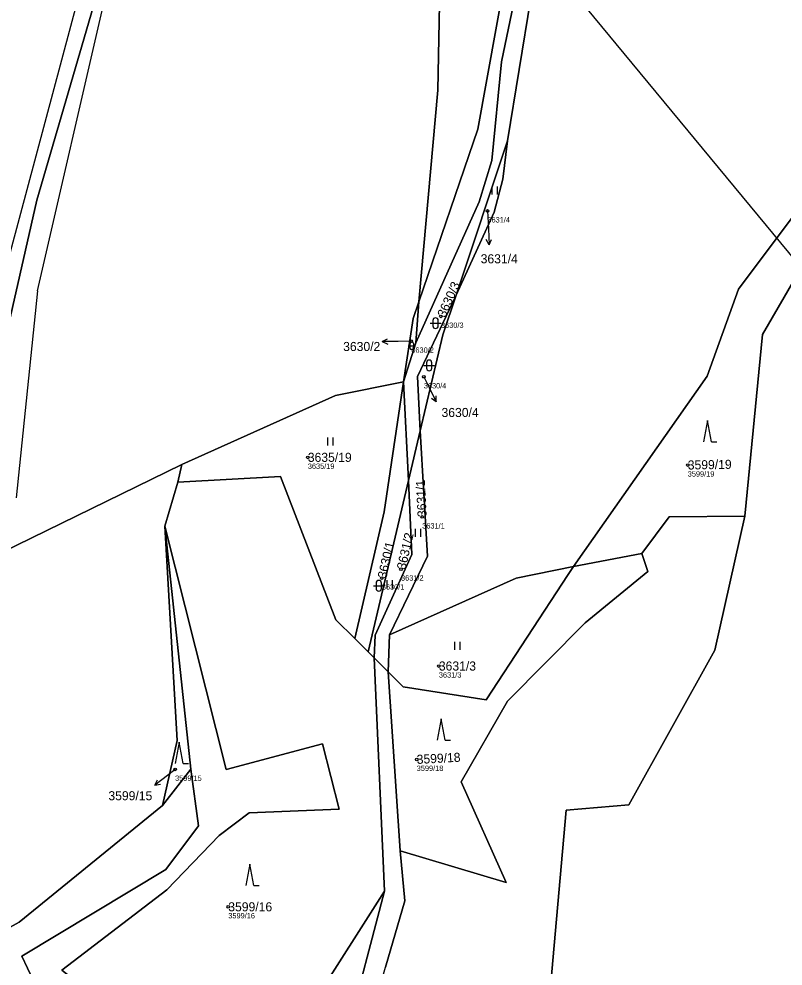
# Model space of a CAD drawing. Extents: x -761174 to -757114, y -1063806 to -1059397.
# Drawn here: x -759812.1 to -759669, y -1062320.9 to -1062143.6 of the extents above; entities that cross this region are included whole.
import ezdxf

# ---------------------------------------------------------------- set-up
doc = ezdxf.new("R2010")
doc.units = 0
for name, color, linetype in [('Definiční body', 7, 'Continuous'), ('Hranice parcel', 7, 'Continuous'), ('Parcelní čísla', 7, 'Continuous'), ('Polygon parcely', 7, 'Continuous'), ('Pop  PČ popisy', 7, 'Continuous'), ('Poz předměty', 7, 'Continuous'), ('Vnitřní kresba', 7, 'Continuous'), ('Značky kultur', 7, 'Continuous')]:
    doc.layers.add(name, color=color, linetype=linetype)

msp = doc.modelspace()

# ---------------------------------------------------------------- linework, layer by layer
at = {"layer": 'Definiční body'}
for centre in [(-759724.36, -1062179.54), (-759733.05, -1062199.28), (-759738.61, -1062203.93), (-759736.27, -1062210.61), (-759757.99, -1062225.68), (-759686.85, -1062227.12), (-759736.57, -1062236.85), (-759740.54, -1062246.61), (-759744.13, -1062248.28), (-759733.45, -1062264.76), (-759737.6, -1062282.25), (-759782.84, -1062284.11), (-759772.88, -1062309.85)]:
    msp.add_circle(centre, 0.25, dxfattribs=at)
at = {"layer": 'Hranice parcel'}
for p, q in [((-759720.61, -1062166.43), (-759716.25, -1062139.61)), ((-759730.24, -1062195.31), (-759720.61, -1062166.43)), ((-759737.74, -1062204.26), (-759737.22, -1062196.58)), ((-759740.05, -1062211.53), (-759737.74, -1062204.26)), ((-759739.14, -1062230.01), (-759740.05, -1062211.53)), ((-759739.14, -1062230.01), (-759736.96, -1062220.72)), ((-759781.6, -1062227.04), (-759815.38, -1062243.59)), ((-759782.35, -1062230.32), (-759781.6, -1062227.04)), ((-759782.35, -1062230.32), (-759784.74, -1062238.57)), ((-759746.7, -1062262.09), (-759739.14, -1062230.01)), ((-759784.74, -1062238.57), (-759779.89, -1062284.06)), ((-759695.44, -1062243.68), (-759708.22, -1062246.11)), ((-759746.7, -1062262.09), (-759749.18, -1062259.62)), ((-759742.96, -1062265.82), (-759742.68, -1062258.9)), ((-759745.54, -1062263.25), (-759746.7, -1062262.09)), ((-759742.96, -1062265.82), (-759745.54, -1062263.25)), ((-759745.54, -1062263.25), (-759743.66, -1062306.91)), ((-759740.67, -1062299.37), (-759742.96, -1062265.82)), ((-759779.89, -1062284.06), (-759785.19, -1062290.87))]:
    msp.add_line(p, q, dxfattribs=at)
for points in [[(-759545.3, -1061775.92), (-759556.69, -1061808.62), (-759569.81, -1061839.63), (-759636.3, -1061992.96), (-759657.95, -1062035.02), (-759667.29, -1062048.77), (-759718.51, -1062136.23), (-759721.74, -1062151.6), (-759723.54, -1062170.11), (-759725.88, -1062177.84), (-759737.74, -1062204.26)], [(-759558.92, -1061800.74), (-759575.13, -1061841.03), (-759591.11, -1061875.72), (-759612.9, -1061925.74), (-759639.46, -1061986.58), (-759648.39, -1062006.27), (-759683.61, -1062069.8), (-759720.86, -1062134.89), (-759726.17, -1062164.23), (-759737.22, -1062196.58)], [(-759815.38, -1062243.59), (-759815.76, -1062232.79), (-759816.51, -1062211.67), (-759808.74, -1062177.53), (-759796.88, -1062136.8), (-759772.79, -1062042.32), (-759754.06, -1061970.78)], [(-759737.22, -1062196.58), (-759733.65, -1062156.94), (-759733.29, -1062137.53), (-759733.29, -1062120.99), (-759730.77, -1062101.04), (-759728.98, -1062091.69), (-759727.54, -1062084.5), (-759716.22, -1062052.87), (-759689.95, -1061989.47)], [(-759730.24, -1062195.31), (-759723.11, -1062179.76), (-759721.45, -1062173.6), (-759720.61, -1062166.43)], [(-759656.65, -1062166.55), (-759677.32, -1062194.16), (-759683.22, -1062210.47), (-759708.22, -1062246.11)], [(-759676.15, -1062236.72), (-759672.84, -1062202.65), (-759655.22, -1062172.34), (-759631.4, -1062166.18)], [(-759736.96, -1062220.72), (-759737.42, -1062210.53), (-759730.24, -1062195.31)], [(-759736.96, -1062220.72), (-759732.72, -1062202.74), (-759730.24, -1062195.31)], [(-759737.22, -1062196.58), (-759738.27, -1062199.65), (-759740.05, -1062211.53)], [(-759781.6, -1062227.04), (-759752.83, -1062214.13), (-759740.05, -1062211.53)], [(-759740.05, -1062211.53), (-759743.7, -1062235.88), (-759749.18, -1062259.62)], [(-759742.68, -1062258.9), (-759735.59, -1062244.19), (-759736.96, -1062220.72)], [(-759749.18, -1062259.62), (-759752.72, -1062256.09), (-759763.1, -1062229.27), (-759782.35, -1062230.32)], [(-759739.14, -1062230.01), (-759738.49, -1062243.89), (-759745.4, -1062258.95), (-759745.54, -1062263.25)], [(-759661.11, -1062333.69), (-759655, -1062355.31), (-759665.48, -1062372.16), (-759707.86, -1062386.9), (-759714.53, -1062347.36), (-759709.59, -1062291.77), (-759697.9, -1062290.77), (-759681.77, -1062261.79), (-759676.15, -1062236.72)], [(-759676.15, -1062236.72), (-759690.31, -1062236.81), (-759695.44, -1062243.68)], [(-759781.89, -1062360.97), (-759792.16, -1062330.99), (-759804.08, -1062321.72), (-759784.37, -1062306.65), (-759774.58, -1062296.47), (-759768.98, -1062292.24), (-759752.09, -1062291.57), (-759755.23, -1062279.32), (-759773.28, -1062284.12), (-759784.74, -1062238.57)], [(-759784.74, -1062238.57), (-759782.46, -1062278.72), (-759785.19, -1062290.87)], [(-759695.44, -1062243.68), (-759694.32, -1062247.04), (-759706.04, -1062256.65), (-759720.57, -1062271.35), (-759729.26, -1062286.46), (-759720.82, -1062305.3), (-759740.67, -1062299.37)], [(-759708.22, -1062246.11), (-759709.26, -1062247.6), (-759724.58, -1062271.1), (-759740.12, -1062268.66), (-759742.96, -1062265.82)], [(-759708.22, -1062246.11), (-759719, -1062248.31), (-759742.68, -1062258.9)], [(-759807.29, -1062328.11), (-759811.57, -1062319.1), (-759784.56, -1062302.86), (-759778.43, -1062294.67), (-759779.89, -1062284.06)], [(-759785.19, -1062290.87), (-759812.06, -1062312.74), (-759841.45, -1062329.06), (-759887.14, -1062348.41), (-759932.19, -1062365.38), (-759967.88, -1062383.64)], [(-760020.59, -1062648.57), (-759995.77, -1062595.56), (-759991.2, -1062568.04), (-759996.63, -1062541.3), (-759992.35, -1062525.36), (-759974.46, -1062506.7), (-759909.51, -1062464.71), (-759859.16, -1062431.43), (-759834.95, -1062413.73), (-759801.17, -1062385.56), (-759794.9, -1062381.81), (-759778.11, -1062375.37), (-759761.36, -1062358.58), (-759747.99, -1062337.03), (-759743.43, -1062321.15), (-759739.84, -1062308.74), (-759740.67, -1062299.37)], [(-759743.66, -1062306.91), (-759750.82, -1062334.23), (-759753.96, -1062339.82), (-759764.09, -1062355.43), (-759780.18, -1062372.22), (-759794.64, -1062378.4)], [(-759781.89, -1062360.97), (-759776.24, -1062342.1), (-759767.38, -1062331.67), (-759756.89, -1062327.68), (-759743.66, -1062306.91)]]:
    msp.add_lwpolyline(points, dxfattribs=at)
at = {"layer": 'Polygon parcely'}
for points in [[(-759558.92, -1061800.74), (-759595.48, -1061771.75), (-759611.84, -1061811.14), (-759629.14, -1061861.06), (-759642.77, -1061894.86), (-759665.68, -1061944.54), (-759687.02, -1061992.16), (-759689.95, -1061989.47), (-759716.22, -1062052.87), (-759727.54, -1062084.5), (-759728.98, -1062091.69), (-759730.77, -1062101.04), (-759733.29, -1062120.99), (-759733.29, -1062137.53), (-759733.65, -1062156.94), (-759737.22, -1062196.58), (-759726.17, -1062164.23), (-759720.86, -1062134.89), (-759683.61, -1062069.8), (-759648.39, -1062006.27), (-759639.46, -1061986.58), (-759612.9, -1061925.74), (-759591.11, -1061875.72), (-759575.13, -1061841.03)], [(-759648.39, -1062006.27), (-759683.61, -1062069.8), (-759720.86, -1062134.89), (-759726.17, -1062164.23), (-759737.22, -1062196.58), (-759737.74, -1062204.26), (-759725.88, -1062177.84), (-759723.54, -1062170.11), (-759721.74, -1062151.6), (-759718.51, -1062136.23), (-759667.29, -1062048.77), (-759657.95, -1062035.02), (-759636.3, -1061992.96), (-759569.81, -1061839.63), (-759556.69, -1061808.62), (-759545.3, -1061775.92), (-759550.13, -1061774.5), (-759553.55, -1061786.76), (-759558.92, -1061800.74), (-759575.13, -1061841.03), (-759591.11, -1061875.72), (-759612.9, -1061925.74), (-759639.46, -1061986.58)], [(-759730.77, -1062101.04), (-759728.98, -1062091.69), (-759727.54, -1062084.5), (-759716.22, -1062052.87), (-759689.95, -1061989.47), (-759687.6, -1061983.6), (-759718.19, -1061977.43), (-759750.64, -1061971.41), (-759754.06, -1061970.78), (-759772.79, -1062042.32), (-759796.88, -1062136.8), (-759808.74, -1062177.53), (-759816.51, -1062211.67), (-759815.76, -1062232.79), (-759815.38, -1062243.59), (-759781.6, -1062227.04), (-759752.83, -1062214.13), (-759740.05, -1062211.53), (-759738.27, -1062199.65), (-759737.22, -1062196.58), (-759733.65, -1062156.94), (-759733.29, -1062137.53), (-759733.29, -1062120.99)], [(-759588.26, -1062010.59), (-759631.6, -1061990.87), (-759640.77, -1062012.48), (-759677.67, -1062073.75), (-759716.25, -1062139.61), (-759720.61, -1062166.43), (-759721.45, -1062173.6), (-759723.11, -1062179.76), (-759730.24, -1062195.31), (-759732.72, -1062202.74), (-759736.96, -1062220.72), (-759735.59, -1062244.19), (-759742.68, -1062258.9), (-759719, -1062248.31), (-759708.22, -1062246.11), (-759683.22, -1062210.47), (-759677.32, -1062194.16), (-759656.65, -1062166.55), (-759629.93, -1062140.56), (-759592.55, -1062105.98), (-759580.43, -1062086.92), (-759557.69, -1062026.84)], [(-759721.45, -1062173.6), (-759720.61, -1062166.43), (-759730.24, -1062195.31), (-759723.11, -1062179.76)], [(-759655.22, -1062172.34), (-759631.4, -1062166.18), (-759656.65, -1062166.55), (-759677.32, -1062194.16), (-759683.22, -1062210.47), (-759708.22, -1062246.11), (-759695.44, -1062243.68), (-759690.31, -1062236.81), (-759676.15, -1062236.72), (-759672.84, -1062202.65)], [(-759736.96, -1062220.72), (-759732.72, -1062202.74), (-759730.24, -1062195.31), (-759737.42, -1062210.53)], [(-759737.74, -1062204.26), (-759737.22, -1062196.58), (-759738.27, -1062199.65), (-759740.05, -1062211.53)], [(-759782.35, -1062230.32), (-759763.1, -1062229.27), (-759752.72, -1062256.09), (-759749.18, -1062259.62), (-759743.7, -1062235.88), (-759740.05, -1062211.53), (-759752.83, -1062214.13), (-759781.6, -1062227.04)], [(-759743.7, -1062235.88), (-759749.18, -1062259.62), (-759746.7, -1062262.09), (-759739.14, -1062230.01), (-759740.05, -1062211.53)], [(-759745.4, -1062258.95), (-759745.54, -1062263.25), (-759742.96, -1062265.82), (-759742.68, -1062258.9), (-759735.59, -1062244.19), (-759736.96, -1062220.72), (-759739.14, -1062230.01), (-759738.49, -1062243.89)], [(-759756.89, -1062327.68), (-759743.66, -1062306.91), (-759745.54, -1062263.25), (-759746.7, -1062262.09), (-759749.18, -1062259.62), (-759752.72, -1062256.09), (-759763.1, -1062229.27), (-759782.35, -1062230.32), (-759784.74, -1062238.57), (-759773.28, -1062284.12), (-759755.23, -1062279.32), (-759752.09, -1062291.57), (-759768.98, -1062292.24), (-759774.58, -1062296.47), (-759784.37, -1062306.65), (-759804.08, -1062321.72), (-759792.16, -1062330.99), (-759781.89, -1062360.97), (-759776.24, -1062342.1), (-759767.38, -1062331.67)], [(-759746.7, -1062262.09), (-759745.54, -1062263.25), (-759745.4, -1062258.95), (-759738.49, -1062243.89), (-759739.14, -1062230.01)], [(-759784.74, -1062238.57), (-759782.46, -1062278.72), (-759785.19, -1062290.87), (-759779.89, -1062284.06)], [(-759740.12, -1062268.66), (-759742.96, -1062265.82), (-759740.67, -1062299.37), (-759720.82, -1062305.3), (-759729.26, -1062286.46), (-759720.57, -1062271.35), (-759706.04, -1062256.65), (-759694.32, -1062247.04), (-759695.44, -1062243.68), (-759708.22, -1062246.11), (-759709.26, -1062247.6), (-759724.58, -1062271.1)], [(-759708.22, -1062246.11), (-759719, -1062248.31), (-759742.68, -1062258.9), (-759742.96, -1062265.82), (-759740.12, -1062268.66), (-759724.58, -1062271.1), (-759709.26, -1062247.6)], [(-759932.19, -1062365.38), (-759967.88, -1062383.64), (-759942.48, -1062419.16), (-760023, -1062468.21), (-760010.32, -1062480.46), (-760000.07, -1062471.78), (-759958.26, -1062448.21), (-759890.08, -1062409.72), (-759837.94, -1062374.87), (-759850.99, -1062357.55), (-759807.29, -1062328.11), (-759811.57, -1062319.1), (-759784.56, -1062302.86), (-759778.43, -1062294.67), (-759779.89, -1062284.06), (-759785.19, -1062290.87), (-759812.06, -1062312.74), (-759841.45, -1062329.06), (-759887.14, -1062348.41)], [(-759794.64, -1062378.4), (-759780.18, -1062372.22), (-759764.09, -1062355.43), (-759753.96, -1062339.82), (-759750.82, -1062334.23), (-759743.66, -1062306.91), (-759756.89, -1062327.68), (-759767.38, -1062331.67), (-759776.24, -1062342.1), (-759781.89, -1062360.97)]]:
    msp.add_lwpolyline(points, close=True, dxfattribs=at)
for points in [[(-759569.81, -1061839.63), (-759636.3, -1061992.96), (-759657.95, -1062035.02), (-759667.29, -1062048.77), (-759718.51, -1062136.23), (-759721.74, -1062151.6), (-759723.54, -1062170.11), (-759725.88, -1062177.84), (-759737.74, -1062204.26), (-759740.05, -1062211.53), (-759739.14, -1062230.01), (-759736.96, -1062220.72), (-759737.42, -1062210.53), (-759730.24, -1062195.31), (-759720.61, -1062166.43), (-759716.25, -1062139.61), (-759666.36, -1062051.73), (-759656.73, -1062037.91), (-759631.6, -1061990.87), (-759555.83, -1061812.6)], [(-759816.51, -1062211.67), (-759808.74, -1062177.53), (-759796.88, -1062136.8), (-759772.79, -1062042.32), (-759754.06, -1061970.78), (-759732.68, -1061896.84)], [(-759662.21, -1062329.2), (-759648.9, -1062270.26), (-759631.44, -1062212.08), (-759635.25, -1062195.55), (-759634.49, -1062185.46), (-759605.51, -1062154.07), (-759594.73, -1062135.75), (-759577.55, -1062116.98), (-759562.6, -1062106.42), (-759557.22, -1062097.26), (-759568.77, -1062107.25), (-759586.12, -1062114.51), (-759603.7, -1062133.56), (-759610.81, -1062145.76), (-759629.98, -1062149.51), (-759631.72, -1062157.82), (-759631.4, -1062166.18), (-759655.22, -1062172.34), (-759672.84, -1062202.65), (-759676.15, -1062236.72), (-759681.77, -1062261.79), (-759697.9, -1062290.77), (-759709.59, -1062291.77), (-759714.53, -1062347.36)], [(-759841.45, -1062329.06), (-759812.06, -1062312.74), (-759785.19, -1062290.87), (-759782.46, -1062278.72), (-759784.74, -1062238.57), (-759782.35, -1062230.32), (-759781.6, -1062227.04), (-759815.38, -1062243.59), (-759827.1, -1062249.52), (-759856.29, -1062267.96), (-759874.47, -1062278.25), (-759899.94, -1062290.42), (-759909.41, -1062270.89), (-759941.52, -1062288.27), (-759942.75, -1062286.38), (-759968.14, -1062295.03), (-760027.57, -1062313.78), (-760098.41, -1062337.59)], [(-759714.53, -1062347.36), (-759709.59, -1062291.77), (-759697.9, -1062290.77), (-759681.77, -1062261.79), (-759676.15, -1062236.72), (-759690.31, -1062236.81), (-759695.44, -1062243.68), (-759694.32, -1062247.04), (-759706.04, -1062256.65), (-759720.57, -1062271.35), (-759729.26, -1062286.46), (-759720.82, -1062305.3), (-759740.67, -1062299.37), (-759739.84, -1062308.74), (-759743.43, -1062321.15)], [(-759804.08, -1062321.72), (-759784.37, -1062306.65), (-759774.58, -1062296.47), (-759768.98, -1062292.24), (-759752.09, -1062291.57), (-759755.23, -1062279.32), (-759773.28, -1062284.12), (-759784.74, -1062238.57), (-759779.89, -1062284.06), (-759778.43, -1062294.67), (-759784.56, -1062302.86), (-759811.57, -1062319.1), (-759807.29, -1062328.11)], [(-759743.43, -1062321.15), (-759739.84, -1062308.74), (-759740.67, -1062299.37), (-759742.96, -1062265.82), (-759745.54, -1062263.25), (-759743.66, -1062306.91), (-759750.82, -1062334.23)]]:
    msp.add_lwpolyline(points, dxfattribs=at)
at = {"layer": 'Pop  PČ popisy'}
for p, q in [((-759724.36, -1062179.54), (-759724.18, -1062182.89)), ((-759724.18, -1062182.89), (-759724.02, -1062185.89)), ((-759724.02, -1062185.89), (-759724.58, -1062184.91)), ((-759724.02, -1062185.89), (-759723.58, -1062184.86)), ((-759744.04, -1062204.01), (-759743.05, -1062203.49)), ((-759741.04, -1062203.96), (-759744.04, -1062204.01)), ((-759744.04, -1062204.01), (-759743.03, -1062204.5)), ((-759738.61, -1062203.93), (-759741.04, -1062203.96)), ((-759736.27, -1062210.61), (-759735.28, -1062212.61)), ((-759735.28, -1062212.61), (-759733.96, -1062215.31)), ((-759733.96, -1062215.31), (-759734.85, -1062214.63)), ((-759733.96, -1062215.31), (-759733.95, -1062214.19)), ((-759782.84, -1062284.11), (-759784.28, -1062285.23)), ((-759784.28, -1062285.23), (-759786.65, -1062287.08)), ((-759786.65, -1062287.08), (-759786.16, -1062286.07)), ((-759786.65, -1062287.08), (-759785.55, -1062286.86))]:
    msp.add_line(p, q, dxfattribs=at)
at = {"layer": 'Poz předměty'}
msp.add_line((-759558.02, -1062320.42), (-759784.85, -1062045.77), dxfattribs=at)
at = {"layer": 'Vnitřní kresba'}
for p, q in [((-759815.09, -1062192.55), (-759798.96, -1062132.08)), ((-759808.61, -1062194.48), (-759794.27, -1062132.35)), ((-759808.61, -1062194.48), (-759812.59, -1062233.25))]:
    msp.add_line(p, q, dxfattribs=at)
at = {"layer": 'Značky kultur'}
for p, q in [((-759723.45, -1062176.48), (-759723.45, -1062174.98)), ((-759722.45, -1062176.48), (-759722.45, -1062174.98)), ((-759735.07, -1062200.56), (-759733.07, -1062200.56)), ((-759734.57, -1062200.06), (-759734.57, -1062201.06)), ((-759733.57, -1062201.06), (-759733.57, -1062200.06)), ((-759739.21, -1062204.81), (-759737.81, -1062204.81)), ((-759738.86, -1062204.46), (-759738.86, -1062205.16)), ((-759738.16, -1062205.16), (-759738.16, -1062204.46)), ((-759736.26, -1062208.47), (-759734.26, -1062208.47)), ((-759735.76, -1062207.97), (-759735.76, -1062208.97)), ((-759734.76, -1062208.97), (-759734.76, -1062207.97)), ((-759683.16, -1062218.75), (-759683.91, -1062222.75)), ((-759682.41, -1062222.75), (-759683.16, -1062218.75)), ((-759754.27, -1062223.48), (-759754.27, -1062221.98)), ((-759753.27, -1062223.48), (-759753.27, -1062221.98)), ((-759682.41, -1062222.75), (-759681.41, -1062222.75)), ((-759737.8, -1062240.57), (-759737.8, -1062239.07)), ((-759736.8, -1062240.57), (-759736.8, -1062239.07)), ((-759745.2, -1062249.22), (-759745.2, -1062250.22)), ((-759744.2, -1062250.22), (-759744.2, -1062249.22)), ((-759743.14, -1062250.21), (-759743.14, -1062248.71)), ((-759742.14, -1062250.21), (-759742.14, -1062248.71)), ((-759745.7, -1062249.72), (-759743.7, -1062249.72)), ((-759730.44, -1062261.72), (-759730.44, -1062260.22)), ((-759729.44, -1062261.72), (-759729.44, -1062260.22)), ((-759732.99, -1062274.65), (-759733.74, -1062278.65)), ((-759732.24, -1062278.65), (-759732.99, -1062274.65)), ((-759782.05, -1062279.01), (-759782.8, -1062283.01)), ((-759781.3, -1062283.01), (-759782.05, -1062279.01)), ((-759732.24, -1062278.65), (-759731.24, -1062278.65)), ((-759781.3, -1062283.01), (-759780.3, -1062283.01)), ((-759768.86, -1062301.84), (-759769.61, -1062305.84)), ((-759768.11, -1062305.84), (-759768.86, -1062301.84)), ((-759768.11, -1062305.84), (-759767.11, -1062305.84))]:
    msp.add_line(p, q, dxfattribs=at)
for centre, radius, start, end in [((-759734.07, -1062200.06), 0.5, 0, 180), ((-759734.07, -1062201.06), 0.5, 180, 359.9879), ((-759738.51, -1062204.46), 0.35, 0, 180), ((-759738.51, -1062205.16), 0.35, 180, 359.9879), ((-759735.26, -1062207.97), 0.5, 0, 180), ((-759735.26, -1062208.97), 0.5, 180, 359.9879), ((-759744.7, -1062249.22), 0.5, 0, 180), ((-759744.7, -1062250.22), 0.5, 180, 359.9879)]:
    msp.add_arc(centre, radius, start, end, dxfattribs=at)

# ---------------------------------------------------------------- texts
at = {"layer": 'Definiční body'}
for s, p in [('3631/4', (-759724.36, -1062181.7)), ('3630/3', (-759733.05, -1062201.44)), ('3630/2', (-759738.61, -1062206.09)), ('3630/4', (-759736.27, -1062212.77)), ('3635/19', (-759757.99, -1062227.84)), ('3599/19', (-759686.85, -1062229.28)), ('3631/1', (-759736.57, -1062239.01)), ('3631/2', (-759740.54, -1062248.77)), ('3630/1', (-759744.13, -1062250.44)), ('3631/3', (-759733.45, -1062266.92)), ('3599/18', (-759737.6, -1062284.41)), ('3599/15', (-759782.84, -1062286.27)), ('3599/16', (-759772.88, -1062312.01))]:
    msp.add_text(s, height=1, dxfattribs=at).set_placement(p)
at = {"layer": 'Parcelní čísla'}
for s, p in [('3631/4', (-759725.62, -1062189.35)), ('3630/2', (-759751.37, -1062205.77)), ('3630/4', (-759732.95, -1062218.13)), ('3635/19', (-759757.99, -1062226.53)), ('3631/3', (-759733.45, -1062265.61)), ('3599/15', (-759795.33, -1062289.9)), ('3599/16', (-759772.88, -1062310.7))]:
    msp.add_text(s, height=1.7, dxfattribs=at).set_placement(p)
for s, rotation, p in [('3630/3', 66, (-759732.27, -1062199.62)), ('3599/19', 1, (-759686.83, -1062227.97)), ('3631/1', 93, (-759735.72, -1062236.8)), ('3631/2', 77, (-759739.71, -1062246.8)), ('3630/1', 77, (-759743.3, -1062248.47)), ('3599/18', 3, (-759737.56, -1062283.1))]:
    msp.add_text(s, height=1.7, rotation=rotation, dxfattribs=at).set_placement(p)

doc.saveas('drawing.dxf')
